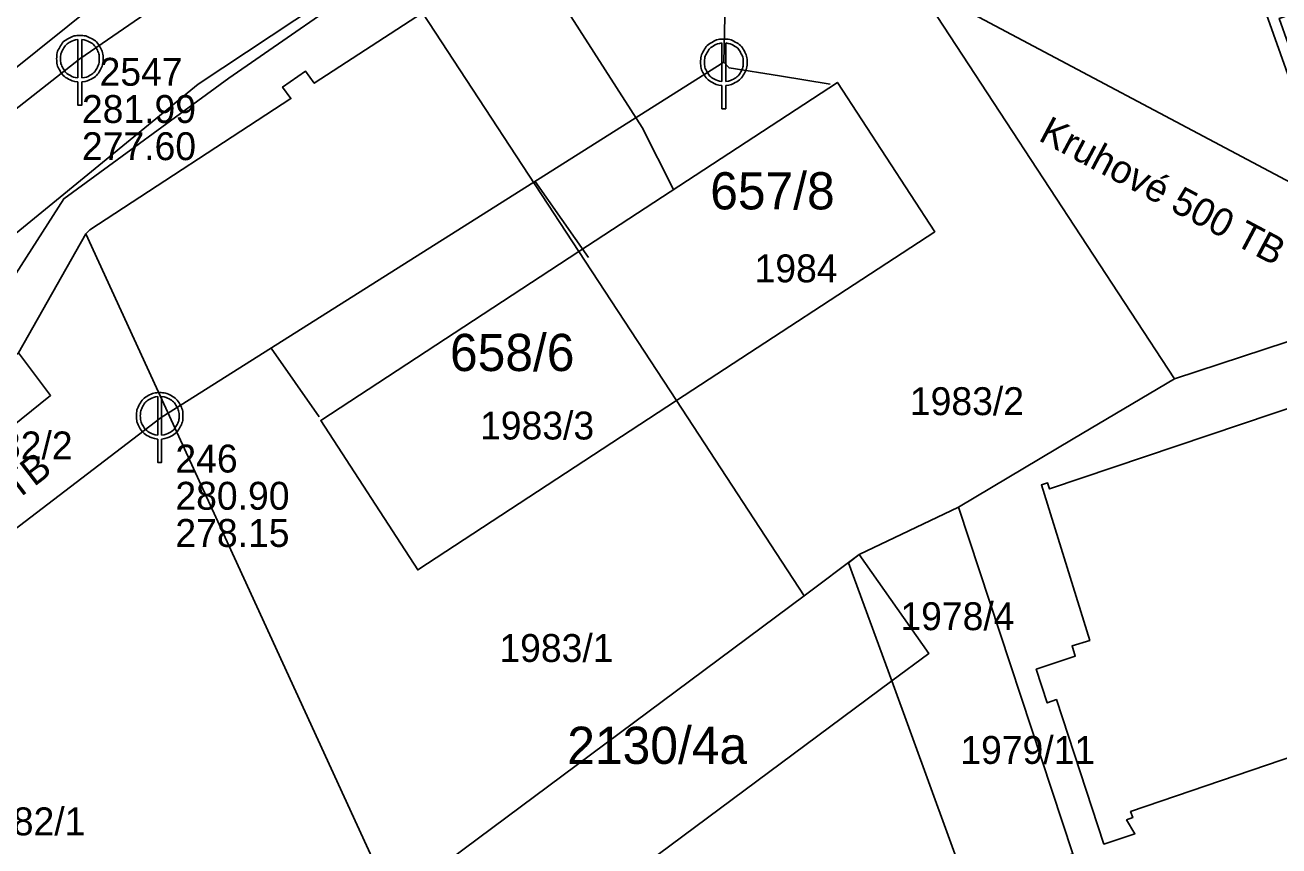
# Model space of a CAD drawing. Extents: x -570698 to -570232, y -1086952 to -1086596.
# Drawn here: x -570431.1 to -570363.7, y -1086825.7 to -1086781.6 of the extents above; entities that cross this region are included whole.
import ezdxf

# ---------------------------------------------------------------- set-up
doc = ezdxf.new("R2010")
doc.units = 0
for name, color, linetype in [('Adresní místo-text', 7, 'Continuous'), ('Default', 7, 'Continuous'), ('Kanalizační přípojka', 7, 'Continuous'), ('Kanalizační stoka', 7, 'Continuous'), ('Kanalizační šachta', 7, 'Continuous'), ('Parcela-polygon', 7, 'Continuous'), ('Parcela-text', 7, 'Continuous'), ('Popis kmenové stoky', 7, 'Continuous'), ('Popis šachty', 7, 'Continuous'), ('Vodovodní přípojka', 7, 'Continuous'), ('Vodovodní řad', 7, 'Continuous')]:
    doc.layers.add(name, color=color, linetype=linetype)

msp = doc.modelspace()

# ---------------------------------------------------------------- linework, layer by layer
at = {"layer": 'Default'}
for points in [[(-570428.303, -1086784.628), (-570428.561, -1086784.61), (-570428.823, -1086784.464), (-570429.12, -1086784.3), (-570429.285, -1086784.003), (-570429.45, -1086783.705), (-570429.45, -1086783.38), (-570429.45, -1086783.053), (-570429.282, -1086782.753), (-570429.113, -1086782.452), (-570428.815, -1086782.291), (-570428.517, -1086782.13), (-570428.2, -1086782.13), (-570427.885, -1086782.13), (-570427.586, -1086782.291), (-570427.287, -1086782.452), (-570427.118, -1086782.753), (-570426.95, -1086783.053), (-570426.95, -1086783.38), (-570426.95, -1086783.705), (-570427.115, -1086784.003), (-570427.28, -1086784.3), (-570427.577, -1086784.464), (-570427.839, -1086784.61), (-570428.097, -1086784.628)], [(-570393.683, -1086784.818), (-570393.941, -1086784.8), (-570394.203, -1086784.654), (-570394.5, -1086784.49), (-570394.665, -1086784.193), (-570394.83, -1086783.895), (-570394.83, -1086783.57), (-570394.83, -1086783.243), (-570394.662, -1086782.943), (-570394.493, -1086782.642), (-570394.195, -1086782.481), (-570393.897, -1086782.32), (-570393.58, -1086782.32), (-570393.265, -1086782.32), (-570392.966, -1086782.481), (-570392.667, -1086782.642), (-570392.498, -1086782.943), (-570392.33, -1086783.243), (-570392.33, -1086783.57), (-570392.33, -1086783.895), (-570392.495, -1086784.193), (-570392.66, -1086784.49), (-570392.957, -1086784.654), (-570393.219, -1086784.8), (-570393.477, -1086784.818)], [(-570428.303, -1086782.342), (-570428.5, -1086782.359), (-570428.715, -1086782.474), (-570428.964, -1086782.609), (-570429.103, -1086782.859), (-570429.242, -1086783.109), (-570429.242, -1086783.38), (-570429.242, -1086783.651), (-570429.106, -1086783.898), (-570428.969, -1086784.144), (-570428.72, -1086784.281), (-570428.508, -1086784.401), (-570428.303, -1086784.415)], [(-570428.097, -1086784.415), (-570427.892, -1086784.401), (-570427.678, -1086784.281), (-570427.431, -1086784.144), (-570427.294, -1086783.898), (-570427.158, -1086783.651), (-570427.158, -1086783.38), (-570427.158, -1086783.109), (-570427.298, -1086782.859), (-570427.438, -1086782.609), (-570427.687, -1086782.474), (-570427.9, -1086782.359), (-570428.097, -1086782.342)], [(-570393.683, -1086782.532), (-570393.88, -1086782.549), (-570394.095, -1086782.664), (-570394.344, -1086782.799), (-570394.483, -1086783.049), (-570394.622, -1086783.299), (-570394.622, -1086783.57), (-570394.622, -1086783.841), (-570394.486, -1086784.088), (-570394.349, -1086784.334), (-570394.1, -1086784.471), (-570393.888, -1086784.591), (-570393.683, -1086784.605)], [(-570393.477, -1086784.605), (-570393.272, -1086784.591), (-570393.058, -1086784.471), (-570392.811, -1086784.334), (-570392.674, -1086784.088), (-570392.538, -1086783.841), (-570392.538, -1086783.57), (-570392.538, -1086783.299), (-570392.678, -1086783.049), (-570392.818, -1086782.799), (-570393.067, -1086782.664), (-570393.28, -1086782.549), (-570393.477, -1086782.532)], [(-570424.013, -1086803.828), (-570424.271, -1086803.81), (-570424.533, -1086803.664), (-570424.83, -1086803.5), (-570424.995, -1086803.203), (-570425.16, -1086802.905), (-570425.16, -1086802.58), (-570425.16, -1086802.253), (-570424.992, -1086801.953), (-570424.823, -1086801.652), (-570424.525, -1086801.491), (-570424.227, -1086801.33), (-570423.91, -1086801.33), (-570423.595, -1086801.33), (-570423.296, -1086801.491), (-570422.997, -1086801.652), (-570422.828, -1086801.953), (-570422.66, -1086802.253), (-570422.66, -1086802.58), (-570422.66, -1086802.905), (-570422.825, -1086803.203), (-570422.99, -1086803.5), (-570423.287, -1086803.664), (-570423.549, -1086803.81), (-570423.807, -1086803.828)], [(-570424.013, -1086801.542), (-570424.21, -1086801.559), (-570424.425, -1086801.674), (-570424.674, -1086801.809), (-570424.813, -1086802.059), (-570424.952, -1086802.309), (-570424.952, -1086802.58), (-570424.952, -1086802.851), (-570424.816, -1086803.098), (-570424.679, -1086803.344), (-570424.43, -1086803.481), (-570424.218, -1086803.601), (-570424.013, -1086803.615)], [(-570423.807, -1086803.615), (-570423.602, -1086803.601), (-570423.388, -1086803.481), (-570423.141, -1086803.344), (-570423.004, -1086803.098), (-570422.868, -1086802.851), (-570422.868, -1086802.58), (-570422.868, -1086802.309), (-570423.008, -1086802.059), (-570423.148, -1086801.809), (-570423.397, -1086801.674), (-570423.61, -1086801.559), (-570423.807, -1086801.542)]]:
    msp.add_open_spline(points, degree=3, dxfattribs=at)
at = {"layer": 'Kanalizační přípojka'}
for points in [[(-570387.87, -1086784.74), (-570390.583, -1086784.305), (-570393.3, -1086783.87), (-570393.58, -1086783.57)], [(-570400.865, -1086794.063), (-570402.296, -1086792.02), (-570403.727, -1086789.977)], [(-570415.335, -1086802.623), (-570416.623, -1086800.778), (-570417.911, -1086798.933)]]:
    msp.add_lwpolyline(points, dxfattribs=at)
at = {"layer": 'Kanalizační stoka'}
for p, q in [((-570387.02, -1086777.34), (-570311.73, -1086817.32)), ((-570456.3, -1086827.43), (-570423.83, -1086802.67))]:
    msp.add_line(p, q, dxfattribs=at)
for points in [[(-570393.58, -1086783.57), (-570393.32, -1086771.325), (-570393.06, -1086759.08)], [(-570428.2, -1086783.38), (-570415.55, -1086774.675), (-570402.9, -1086765.97)], [(-570450.31, -1086800.72), (-570439.255, -1086792.05), (-570428.2, -1086783.38)], [(-570423.83, -1086802.67), (-570393.58, -1086783.57)]]:
    msp.add_lwpolyline(points, dxfattribs=at)
at = {"layer": 'Kanalizační šachta'}
for points in [[(-570428.303, -1086784.415), (-570428.303, -1086782.342)], [(-570428.097, -1086782.342), (-570428.097, -1086784.415)], [(-570393.683, -1086784.605), (-570393.683, -1086782.532)], [(-570393.477, -1086782.532), (-570393.477, -1086784.605)], [(-570428.097, -1086784.628), (-570428.097, -1086785.88), (-570428.303, -1086785.88), (-570428.303, -1086784.628)], [(-570393.477, -1086784.818), (-570393.477, -1086786.07), (-570393.683, -1086786.07), (-570393.683, -1086784.818)], [(-570424.013, -1086803.615), (-570424.013, -1086801.542)], [(-570423.807, -1086801.542), (-570423.807, -1086803.615)], [(-570423.807, -1086803.828), (-570423.807, -1086805.08), (-570424.013, -1086805.08), (-570424.013, -1086803.828)]]:
    msp.add_lwpolyline(points, dxfattribs=at)
at = {"layer": 'Parcela-polygon'}
for points in [[(-570471.26, -1086826.6), (-570461.73, -1086819.28), (-570457.91, -1086816.88), (-570450.83, -1086812.94), (-570436.06, -1086800.74), (-570433.95, -1086798.53), (-570429.07, -1086790.91), (-570420.2, -1086784.42), (-570412, -1086778.75), (-570347.1, -1086736.01), (-570341.15, -1086732.35), (-570332.8, -1086726.72), (-570301.2, -1086706.16), (-570286.13, -1086695.6), (-570286.027, -1086695.53)], [(-570347.1, -1086736.01), (-570412, -1086778.75), (-570420.2, -1086784.42), (-570429.07, -1086790.91), (-570433.95, -1086798.53)], [(-570431.51, -1086799.19), (-570427.89, -1086792.8), (-570427.66, -1086792.57), (-570416.86, -1086785.52), (-570417.3, -1086784.9), (-570416.07, -1086784.05), (-570415.6, -1086784.7), (-570409.79, -1086780.91), (-570403.65, -1086776.9), (-570404.13, -1086776.08), (-570402.97, -1086775.36), (-570402.46, -1086776.13), (-570390.48, -1086768.31), (-570384.41, -1086764.61), (-570376.06, -1086759.12), (-570374.88, -1086758.41), (-570374.67, -1086758.28), (-570372.92, -1086757.22), (-570360.33, -1086749.01)], [(-570314.466, -1086822.423), (-570326.4, -1086786.46), (-570358.49, -1086797.03), (-570369.36, -1086800.59), (-570374.8, -1086803.82), (-570380.97, -1086807.48), (-570374.82, -1086826.12), (-570380.47, -1086828.04), (-570398.24, -1086834.1), (-570397.51, -1086836.02), (-570406.58, -1086839.09), (-570441.99, -1086865.7), (-570438.81, -1086873.31), (-570432.93, -1086886.42), (-570435.2, -1086888.38), (-570429.44, -1086901.1), (-570427.788, -1086909.426)], [(-570333.24, -1086792.07), (-570376.07, -1086806.51), (-570376.18, -1086806.18), (-570376.51, -1086806.29), (-570373.91, -1086814.65), (-570374.86, -1086814.95), (-570374.69, -1086815.5), (-570376.79, -1086816.2), (-570376.2, -1086818.01), (-570375.7, -1086817.83), (-570373.15, -1086825.6), (-570371.48, -1086825.05), (-570371.93, -1086824.3), (-570371.6, -1086824.18), (-570371.72, -1086823.85), (-570351.41, -1086816.93)], [(-570374.69, -1086815.5), (-570374.86, -1086814.95), (-570373.91, -1086814.65), (-570376.51, -1086806.29), (-570376.18, -1086806.18), (-570376.07, -1086806.51), (-570333.24, -1086792.07)], [(-570351.41, -1086816.93), (-570371.72, -1086823.85), (-570371.6, -1086824.18), (-570371.93, -1086824.3), (-570371.48, -1086825.05), (-570373.15, -1086825.6), (-570375.7, -1086817.83), (-570376.2, -1086818.01), (-570376.79, -1086816.2), (-570374.69, -1086815.5)]]:
    msp.add_lwpolyline(points, dxfattribs=at)
for points in [[(-570358.49, -1086797.03), (-570359.7, -1086794.79), (-570360.95, -1086790.81), (-570361.2, -1086790.01), (-570364.41, -1086781.01), (-570365.42, -1086778.19), (-570363.46, -1086777.55), (-570369.78, -1086766.25), (-570371.5, -1086763.53), (-570374.88, -1086758.41), (-570376.06, -1086759.12), (-570384.41, -1086764.61), (-570390.48, -1086768.31), (-570369.36, -1086800.59)], [(-570382.24, -1086792.68), (-570396.13, -1086801.76), (-570389.26, -1086812.25), (-570386.31, -1086810.04), (-570380.97, -1086807.48), (-570374.8, -1086803.82), (-570369.36, -1086800.59), (-570390.48, -1086768.31), (-570402.46, -1086776.13), (-570402.97, -1086775.36), (-570404.13, -1086776.08), (-570403.65, -1086776.9), (-570409.79, -1086780.91), (-570401.38, -1086793.74), (-570387.48, -1086784.65)], [(-570331.91, -1086770.3), (-570364.41, -1086781.01), (-570361.2, -1086790.01), (-570360.86, -1086789.89), (-570363.24, -1086782.57), (-570363.72, -1086781.21), (-570353.74, -1086777.77), (-570353.01, -1086780), (-570337.03, -1086774.66), (-570331.69, -1086772.87), (-570331.11, -1086772.68)], [(-570389.26, -1086812.25), (-570396.13, -1086801.76), (-570410.04, -1086810.86), (-570415.25, -1086802.82), (-570401.38, -1086793.74), (-570409.79, -1086780.91), (-570415.6, -1086784.7), (-570416.07, -1086784.05), (-570417.3, -1086784.9), (-570416.86, -1086785.52), (-570427.66, -1086792.57), (-570427.89, -1086792.8), (-570411.39, -1086828.72)], [(-570401.38, -1086793.74), (-570396.13, -1086801.76), (-570382.24, -1086792.68), (-570387.48, -1086784.65)], [(-570427.89, -1086792.8), (-570431.51, -1086799.19), (-570429.78, -1086801.48), (-570439.91, -1086809.64), (-570441.11, -1086808.13), (-570451.49, -1086816.45), (-570459.6, -1086820.01), (-570460.99, -1086822.22), (-570453.71, -1086837.46), (-570440.45, -1086850.62), (-570435.34, -1086846.66), (-570430.85, -1086843.19), (-570411.39, -1086828.72)], [(-570415.25, -1086802.82), (-570410.04, -1086810.86), (-570396.13, -1086801.76), (-570401.38, -1086793.74)], [(-570431.51, -1086799.19), (-570441.63, -1086807.48), (-570441.11, -1086808.13), (-570439.91, -1086809.64), (-570429.78, -1086801.48)], [(-570374.82, -1086826.12), (-570380.97, -1086807.48), (-570386.31, -1086810.04), (-570382.57, -1086815.36), (-570384.55, -1086816.83), (-570380.47, -1086828.04)], [(-570411.39, -1086828.72), (-570430.85, -1086843.19), (-570425.9, -1086850.06), (-570421.23, -1086846.55), (-570416.43, -1086842.95), (-570417.57, -1086841.37), (-570411, -1086836.49), (-570384.55, -1086816.83), (-570382.57, -1086815.36), (-570386.31, -1086810.04), (-570389.26, -1086812.25)], [(-570386.88, -1086810.48), (-570384.55, -1086816.83), (-570382.57, -1086815.36), (-570386.31, -1086810.04)], [(-570380.47, -1086828.04), (-570384.55, -1086816.83), (-570411, -1086836.49), (-570410.21, -1086838.75), (-570408.83, -1086837.72), (-570398.24, -1086834.1)]]:
    msp.add_lwpolyline(points, close=True, dxfattribs=at)
at = {"layer": 'Vodovodní přípojka'}
for points in [[(-570397.967, -1086787.082), (-570403.932, -1086777.752), (-570406.307, -1086773.825)], [(-570397.967, -1086787.082), (-570396.309, -1086790.378)]]:
    msp.add_lwpolyline(points, dxfattribs=at)
at = {"layer": 'Vodovodní řad'}
for points in [[(-570429.328, -1086757.943), (-570424.039, -1086777.75), (-570480.425, -1086822.995), (-570494.455, -1086835.799), (-570516.511, -1086852.784), (-570525.384, -1086857.882), (-570544.749, -1086867.64), (-570545.576, -1086868.114)], [(-570444.41, -1086803.214), (-570444.401, -1086803.207), (-570421.849, -1086784.741), (-570412.714, -1086778.693), (-570406.307, -1086773.825), (-570405.938, -1086773.545), (-570404.787, -1086770.537), (-570403.975, -1086765.833), (-570401.894, -1086760.781)]]:
    msp.add_lwpolyline(points, dxfattribs=at)

# ---------------------------------------------------------------- texts
at = {"layer": 'Adresní místo-text'}
for s, p in [('657/8', (-570394.315, -1086791.48)), ('658/6', (-570408.305, -1086800.17)), ('2130/4a', (-570401.998, -1086821.29))]:
    msp.add_text(s, height=2, dxfattribs=at).set_placement(p)
at = {"layer": 'Parcela-text'}
for s, p in [('1984', (-570391.93, -1086795.4)), ('1983/2', (-570383.58, -1086802.54)), ('1983/3', (-570406.69, -1086803.85)), ('1982/2', (-570434.73, -1086804.92)), ('1978/4', (-570384.09, -1086814.1)), ('1983/1', (-570405.65, -1086815.81)), ('1979/11', (-570380.87, -1086821.29)), ('1982/1', (-570434.04, -1086825.13))]:
    msp.add_text(s, height=1.5, dxfattribs=at).set_placement(p)
at = {"layer": 'Popis kmenové stoky'}
for rotation, p in [(332.0311, (-570376.73, -1086787.741)), (37.49585, (-570441.107, -1086814.427))]:
    msp.add_text('Kruhové 500 TB', height=1.5, rotation=rotation, dxfattribs=at).set_placement(p)
at = {"layer": 'Popis šachty'}
for s, p in [('2547', (-570427.142, -1086784.832)), ('281.99', (-570428.091, -1086786.832)), ('277.60', (-570428.091, -1086788.832)), ('246', (-570423.067, -1086805.626)), ('280.90', (-570423.067, -1086807.626)), ('278.15', (-570423.067, -1086809.626))]:
    msp.add_text(s, height=1.5, dxfattribs=at).set_placement(p)

doc.saveas('drawing.dxf')
